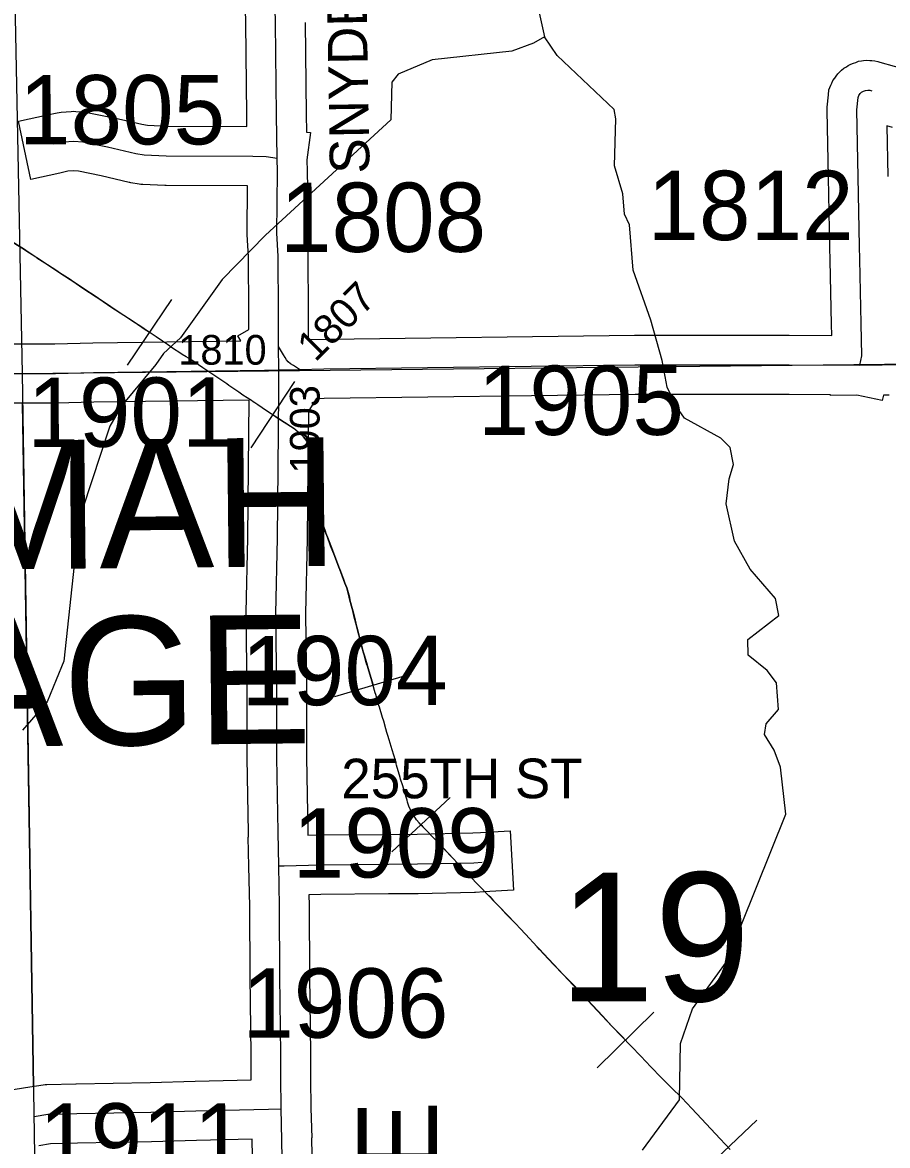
# Model space of a CAD drawing. Extents: x 23.6 to 68.7, y -63 to -29.
# Drawn here: x 50.662 to 51.536, y -49.268 to -48.134 of the extents above; entities that cross this region are included whole.
import ezdxf

# ---------------------------------------------------------------- set-up
doc = ezdxf.new("R2010")
doc.units = 0
for name, color, linetype in [('tdCoCorpTxt', 7, 'Continuous'), ('tdCoHydroRiver', 7, 'Continuous'), ('tdCoPipe', 7, 'Continuous'), ('tdCoSecRdNmbr', 7, 'Continuous'), ('tdCoSecRdTxt', 7, 'Continuous'), ('tdCoSecRteBand', 7, 'Continuous'), ('tdCoSecRteCL', 7, 'Continuous'), ('tdCoSectLine', 7, 'Continuous'), ('tdCoSectLinePart', 7, 'Continuous'), ('tdCoSectNmbr', 7, 'Continuous'), ('tdCoSurfGravel', 7, 'Continuous'), ('tdCoTwpBndry', 7, 'Continuous'), ('tdCoTwpBndryShd', 7, 'Continuous')]:
    doc.layers.add(name, color=color, linetype=linetype)

msp = doc.modelspace()

# ---------------------------------------------------------------- linework, layer by layer
at = {"layer": 'tdCoHydroRiver'}
for points in [[(51.5168, -47.6063), (51.4729, -47.6305), (51.4429, -47.6356), (51.4303, -47.6325), (51.4129, -47.6312), (51.415, -47.6848), (51.4042, -47.7054), (51.384, -47.7309), (51.2793, -47.8331), (51.2543, -47.8492), (51.2121, -47.8922), (51.1935, -47.9209), (51.1972, -47.9698), (51.1862, -47.9809), (51.1723, -48.0079), (51.1697, -48.0585), (51.1897, -48.1482)], [(51.1897, -48.1482), (51.1787, -48.1546), (51.1567, -48.1628), (51.0763, -48.1716), (51.0417, -48.1861), (51.0355, -48.1941), (51.0343, -48.232), (50.9077, -48.3486), (50.864, -48.3933), (50.822, -48.4522), (50.8048, -48.4681), (50.7971, -48.4793), (50.7628, -48.5207), (50.7504, -48.5414), (50.7229, -48.6253), (50.7185, -48.6522), (50.717, -48.6601), (50.7041, -48.7787), (50.6964, -48.7977), (50.6871, -48.8199), (50.6622, -48.8486)], [(51.2888, -49.2726), (51.3261, -49.2217), (51.3271, -49.1649), (51.3393, -49.13), (51.3735, -49.0823), (51.4335, -48.9332), (51.4282, -48.8859), (51.4217, -48.8686), (51.412, -48.853), (51.4135, -48.8419), (51.426, -48.8276), (51.4241, -48.8007), (51.4145, -48.7882), (51.3954, -48.7726), (51.3952, -48.7569), (51.4265, -48.7328), (51.4232, -48.7155), (51.3976, -48.6858), (51.3815, -48.6576), (51.3732, -48.6198), (51.3761, -48.5945), (51.3807, -48.5802), (51.3773, -48.5629), (51.3677, -48.5535), (51.3312, -48.5334), (51.3232, -48.5224), (51.3135, -48.502), (51.3085, -48.4752), (51.297, -48.4343), (51.2791, -48.384), (51.2754, -48.3383), (51.2705, -48.3273), (51.2687, -48.3068), (51.2605, -48.2785), (51.2616, -48.2311), (51.2599, -48.2216), (51.2025, -48.167), (51.1897, -48.1482)]]:
    msp.add_lwpolyline(points, dxfattribs=at)
at = {"layer": 'tdCoPipe'}
for p, q in [((50.7683, -48.4799), (50.8131, -48.4134)), ((50.8934, -48.5635), (50.9374, -48.4965)), ((50.978, -48.8143), (51.0549, -48.7916)), ((51.0355, -48.9712), (51.0943, -48.9166)), ((51.2428, -49.1895), (51.3001, -49.1334)), ((51.3461, -49.2973), (51.4043, -49.2422))]:
    msp.add_line(p, q, dxfattribs=at)
for points in [[(51.3772, -49.272), (51.3671, -49.2613), (51.3576, -49.2511), (51.3482, -49.2408), (51.3385, -49.2304), (51.3284, -49.2198), (51.3178, -49.2094), (51.3075, -49.1991), (51.2972, -49.1883), (51.2871, -49.1777), (51.2773, -49.1676), (51.2679, -49.1579), (51.2577, -49.1473), (51.248, -49.1371), (51.2383, -49.1266), (51.2282, -49.1158), (51.2187, -49.1059), (51.2084, -49.0953), (51.1989, -49.0852), (51.189, -49.0746), (51.1846, -49.0698), (51.1824, -49.0674), (51.1783, -49.0628), (51.1744, -49.0587), (51.1705, -49.0546), (51.165, -49.0488), (51.1608, -49.0442), (51.1593, -49.0428), (51.1524, -49.0357), (51.1506, -49.0338), (51.1451, -49.0279), (51.1405, -49.0232), (51.1382, -49.0208), (51.1343, -49.0167), (51.1313, -49.0136), (51.1253, -49.0073), (51.122, -49.0039), (51.1152, -48.9968), (51.1117, -48.9931), (51.1014, -48.9824), (51.0976, -48.9784), (51.0874, -48.9677), (51.0833, -48.9634), (51.0771, -48.9569), (51.0754, -48.9552), (51.072, -48.9516), (51.0682, -48.9475), (51.0668, -48.9461), (51.0655, -48.9447), (51.063, -48.9419), (51.0603, -48.9389), (51.0568, -48.933), (51.0549, -48.9298), (51.053, -48.9262), (51.0514, -48.9212), (51.0508, -48.9191), (51.0499, -48.916), (51.0471, -48.9069), (51.0464, -48.9047), (51.0443, -48.8978), (51.0439, -48.8962), (51.0403, -48.8839), (51.0399, -48.8825), (51.0397, -48.8812), (51.039, -48.8791), (51.0358, -48.8683), (51.0328, -48.8582), (51.0315, -48.8539), (51.0305, -48.8509), (51.0295, -48.847), (51.0272, -48.8395), (51.026, -48.8355), (51.0229, -48.8251), (51.0224, -48.8234), (51.0192, -48.8124), (51.0187, -48.8108), (51.0145, -48.7964), (51.0122, -48.7885), (51.0107, -48.7838), (51.0103, -48.7825), (51.0096, -48.7801), (51.0074, -48.7724), (51.0065, -48.7694), (51.0057, -48.7668), (51.0027, -48.7549), (51.002, -48.7523), (51, -48.7445), (50.9994, -48.7417), (50.999, -48.7404), (50.9975, -48.7343), (50.9959, -48.728), (50.9952, -48.7255), (50.993, -48.7172), (50.9924, -48.7143), (50.9899, -48.7048), (50.988, -48.6999), (50.9866, -48.6962), (50.9828, -48.6862), (50.9819, -48.6839), (50.9774, -48.6722), (50.9736, -48.6622), (50.9704, -48.6537), (50.9687, -48.6496), (50.9682, -48.6483), (50.9659, -48.6416), (50.965, -48.6367), (50.9647, -48.6338), (50.9641, -48.6295), (50.9631, -48.6225), (50.9627, -48.619), (50.962, -48.6144), (50.9606, -48.6042), (50.9604, -48.6023), (50.9598, -48.5986), (50.9587, -48.5894), (50.9582, -48.5849), (50.9575, -48.5802), (50.9567, -48.5751), (50.9552, -48.569), (50.9533, -48.5633), (50.9509, -48.5586), (50.9488, -48.5556), (50.9462, -48.5522), (50.9424, -48.5488), (50.9408, -48.5475), (50.9365, -48.5439), (50.9328, -48.5415), (50.9204, -48.5334), (50.9079, -48.5252), (50.9044, -48.5228), (50.8999, -48.52), (50.8969, -48.518), (50.8954, -48.517), (50.8935, -48.5157), (50.885, -48.51), (50.8809, -48.5072), (50.8709, -48.5004), (50.8686, -48.4988), (50.8565, -48.4906), (50.8444, -48.4824), (50.8323, -48.4743), (50.8278, -48.4713), (50.8237, -48.469), (50.8212, -48.4674), (50.8148, -48.4632), (50.8088, -48.4591), (50.8037, -48.4556), (50.7974, -48.4513), (50.7853, -48.4431), (50.7828, -48.4414), (50.7729, -48.435), (50.7607, -48.427), (50.7515, -48.4208), (50.7482, -48.4186), (50.7392, -48.4127), (50.7368, -48.411), (50.7243, -48.4029), (50.7198, -48.3997), (50.7119, -48.3944), (50.7105, -48.3935), (50.6998, -48.3866), (50.6971, -48.3847), (50.6874, -48.3784), (50.6769, -48.3715), (50.6757, -48.3707), (50.6656, -48.364), (50.6643, -48.3632), (50.652, -48.3552)], [(50.652, -48.3552), (50.6644, -48.3632), (50.6656, -48.364), (50.6757, -48.3706), (50.6769, -48.3714), (50.6874, -48.3783), (50.6971, -48.3847), (50.6999, -48.3865), (50.7105, -48.3934), (50.712, -48.3944), (50.7198, -48.3997), (50.7244, -48.4028), (50.7368, -48.4109), (50.7393, -48.4127), (50.7482, -48.4186), (50.7515, -48.4208), (50.7608, -48.427), (50.773, -48.4349), (50.7828, -48.4414), (50.7853, -48.443), (50.7907, -48.4467)], [(50.9154, -48.53), (50.9204, -48.5333), (50.9329, -48.5415), (50.9366, -48.5438), (50.9408, -48.5475), (50.9425, -48.5488), (50.9462, -48.5521), (50.9488, -48.5555), (50.9509, -48.5586), (50.9534, -48.5633), (50.9553, -48.569), (50.9568, -48.5751), (50.9576, -48.5802), (50.9583, -48.5849), (50.9588, -48.5894), (50.9599, -48.5986), (50.9605, -48.6023), (50.9606, -48.6042), (50.9621, -48.6144), (50.9627, -48.619), (50.9632, -48.6225), (50.9642, -48.6295), (50.9647, -48.6338), (50.9651, -48.6367), (50.966, -48.6416), (50.9683, -48.6483), (50.9688, -48.6496), (50.9705, -48.6537), (50.9737, -48.6622), (50.9775, -48.6722), (50.982, -48.6839), (50.9828, -48.6861), (50.9866, -48.6961), (50.9881, -48.6999), (50.9899, -48.7048), (50.9925, -48.7142), (50.9931, -48.7172), (50.9953, -48.7255), (50.9959, -48.728), (50.9976, -48.7342), (50.9991, -48.7404), (50.9994, -48.7417), (51.0001, -48.7445), (51.0021, -48.7523), (51.0028, -48.7548), (51.0058, -48.7668), (51.0065, -48.7694), (51.0074, -48.7724), (51.0097, -48.7801), (51.0104, -48.7825), (51.0107, -48.7837), (51.0122, -48.7885), (51.0145, -48.7964), (51.0165, -48.8029)], [(51.0649, -48.9439), (51.0656, -48.9447), (51.0669, -48.946), (51.0682, -48.9475), (51.0721, -48.9515), (51.0755, -48.9551), (51.0771, -48.9569), (51.0833, -48.9633), (51.0875, -48.9677), (51.0976, -48.9783), (51.1015, -48.9823), (51.1117, -48.9931), (51.1152, -48.9968), (51.1221, -49.0039), (51.1253, -49.0072), (51.1314, -49.0136), (51.1343, -49.0166), (51.1382, -49.0208), (51.1405, -49.0232), (51.1451, -49.0279), (51.1506, -49.0337), (51.1525, -49.0357), (51.1594, -49.0427), (51.1608, -49.0441), (51.1651, -49.0488), (51.1705, -49.0545), (51.1744, -49.0587), (51.1783, -49.0628), (51.1824, -49.0673), (51.1847, -49.0697), (51.1891, -49.0745), (51.199, -49.0851), (51.2085, -49.0952), (51.2188, -49.1058), (51.2283, -49.1157), (51.2384, -49.1266), (51.2481, -49.137), (51.2577, -49.1473), (51.268, -49.1579), (51.2714, -49.1614)]]:
    msp.add_lwpolyline(points, dxfattribs=at)
at = {"layer": 'tdCoSecRteBand'}
for points in [[(50.6469, -48.4583), (50.6951, -48.4583), (50.7332, -48.4573), (50.7333, -48.4573), (50.7335, -48.4573), (50.8829, -48.4552), (50.88, -48.4503), (50.8909, -48.4438), (50.8908, -48.4266), (50.8908, -48.4265), (50.8908, -48.4265), (50.8905, -48.3706), (50.8893, -48.3479), (50.8893, -48.347), (50.8893, -48.3462), (50.8897, -48.2988), (50.8074, -48.2985), (50.8068, -48.2985), (50.8062, -48.2985), (50.7839, -48.2975), (50.7819, -48.2974), (50.78, -48.2971), (50.7716, -48.2956), (50.7708, -48.2955), (50.7701, -48.2953), (50.7417, -48.2888), (50.719, -48.284), (50.7141, -48.2836), (50.708, -48.2841), (50.7001, -48.2858), (50.6708, -48.2922), (50.6581, -48.2335), (50.6874, -48.2272), (50.6973, -48.2251), (50.6993, -48.2246), (50.7013, -48.2245), (50.7116, -48.2237), (50.7139, -48.2235), (50.7161, -48.2236), (50.7253, -48.2243), (50.7274, -48.2244), (50.7294, -48.2249), (50.7544, -48.2301), (50.7546, -48.2302), (50.7549, -48.2302), (50.7828, -48.2366), (50.7885, -48.2376), (50.8083, -48.2385), (50.889, -48.2388), (50.8888, -48.2274), (50.8888, -48.2273), (50.8888, -48.2272), (50.888, -48.1346), (50.8857, -48.0332)], [(50.948, -48.1337), (50.948, -48.1339), (50.9488, -48.2265), (50.9491, -48.2445), (50.9533, -48.245), (50.9496, -48.2725), (50.9498, -48.2841), (50.9498, -48.2845), (50.9501, -48.3003), (50.9497, -48.3003), (50.9493, -48.3458), (50.9504, -48.3683), (50.9505, -48.3689), (50.9505, -48.3696), (50.9508, -48.4261), (50.9508, -48.4307), (50.9509, -48.4307), (50.951, -48.4455), (50.951, -48.4455), (50.951, -48.4456), (50.951, -48.4526), (50.9518, -48.4539), (50.9717, -48.4535), (50.9717, -48.4536), (51.2805, -48.4494), (51.2807, -48.4494), (51.2809, -48.4494), (51.4368, -48.4494), (51.4369, -48.4494), (51.437, -48.4494), (51.4799, -48.4498), (51.4797, -48.4384), (51.4784, -48.3741), (51.4779, -48.3607), (51.4779, -48.3605), (51.4779, -48.3602), (51.4766, -48.2905), (51.4753, -48.2226), (51.4752, -48.221), (51.4754, -48.2193), (51.4765, -48.2067), (51.477, -48.2017), (51.479, -48.1971), (51.4799, -48.1952), (51.4811, -48.1924), (51.4829, -48.1899), (51.4842, -48.1881), (51.486, -48.1857), (51.4882, -48.1836), (51.4898, -48.1821), (51.4921, -48.18), (51.4947, -48.1785), (51.4965, -48.1774), (51.4991, -48.1758), (51.502, -48.1748), (51.5041, -48.1741), (51.507, -48.173), (51.51, -48.1726), (51.5121, -48.1723), (51.5151, -48.1719), (51.5182, -48.1721), (51.5204, -48.1723), (51.5234, -48.1725), (51.5263, -48.1733), (51.5284, -48.1739), (51.5573, -48.1819)], [(51.5413, -48.2397), (51.5356, -48.2382), (51.5366, -48.2893)], [(50.64, -49.2134), (50.6697, -49.2088), (50.6832, -49.2067), (50.6851, -49.2064), (50.687, -49.2064), (50.7162, -49.2056), (50.7164, -49.2056), (50.7165, -49.2056), (50.7912, -49.2041), (50.8367, -49.2029), (50.8367, -49.2029), (50.8367, -49.2029), (50.8933, -49.2015), (50.8933, -49.1988), (50.8933, -49.1986), (50.8933, -49.1984), (50.8933, -49.1757), (50.8923, -49.0973), (50.8923, -49.0972), (50.8923, -49.0971), (50.8919, -49.0261), (50.8911, -48.9862), (50.8902, -48.9564), (50.8906, -48.9564), (50.8905, -48.952), (50.8905, -48.952), (50.8905, -48.9519), (50.8893, -48.8766), (50.8893, -48.8764), (50.8893, -48.8761), (50.8893, -48.8094), (50.8882, -48.7309), (50.8882, -48.7303), (50.8882, -48.7297), (50.89, -48.6542), (50.8906, -48.5835), (50.8912, -48.5151), (50.7345, -48.5173), (50.6962, -48.5183), (50.6959, -48.5183), (50.6955, -48.5183), (50.6471, -48.5183)], [(51.5378, -48.5102), (51.5321, -48.5102), (51.5309, -48.5157), (51.5051, -48.5101), (51.4786, -48.5105), (51.4786, -48.5098), (51.4367, -48.5094), (51.2811, -48.5094), (50.9672, -48.5136), (50.9591, -48.5138), (50.9517, -48.5255), (50.9511, -48.5251), (50.9506, -48.5841), (50.9506, -48.5841), (50.9506, -48.5841), (50.95, -48.655), (50.95, -48.6552), (50.95, -48.6554), (50.9482, -48.7306), (50.9493, -48.8088), (50.9493, -48.809), (50.9493, -48.8092), (50.9493, -48.8759), (50.9505, -48.9509), (50.9505, -48.9546), (50.9625, -48.9543), (50.9628, -48.9543), (50.9631, -48.9543), (51.0316, -48.9538), (51.0317, -48.9538), (51.0317, -48.9538), (51.061, -48.9536), (51.1171, -48.9523), (51.125, -48.9519), (51.1549, -48.9501), (51.1584, -49.01), (51.1285, -49.0118), (51.1201, -49.0123), (51.1196, -49.0123), (51.119, -49.0123), (51.0621, -49.0136), (51.0619, -49.0136), (51.0616, -49.0136), (51.032, -49.0138), (50.9638, -49.0143), (50.9517, -49.0146), (50.9517, -49.0149), (50.9519, -49.0251), (50.9519, -49.0254), (50.9519, -49.0256), (50.9523, -49.0967), (50.9533, -49.1751), (50.9533, -49.1753), (50.9533, -49.1755), (50.9533, -49.1982), (50.9533, -49.2004), (50.9537, -49.2302), (50.9545, -49.26), (50.9542, -49.26), (50.9554, -49.3144)], [(50.8954, -49.3156), (50.8942, -49.2615), (50.8382, -49.2629), (50.7927, -49.2641), (50.7926, -49.2641), (50.7925, -49.2641), (50.7178, -49.2656), (50.6905, -49.2663), (50.6788, -49.2681)]]:
    msp.add_lwpolyline(points, dxfattribs=at)
at = {"layer": 'tdCoSecRteCL'}
for q in [(50.921, -48.4609), (50.9423, -48.4841)]:
    msp.add_line((50.9212, -48.4846), q, dxfattribs=at)
for points in [[(50.9196, -48.2708), (50.9188, -48.2269), (50.918, -48.1342), (50.9157, -48.0326), (50.9144, -47.9535), (50.9136, -47.8802), (50.9122, -47.8026), (50.9118, -47.7467)], [(51.5081, -48.48), (51.5102, -48.4703), (51.5097, -48.4379), (51.5084, -48.3733), (51.5079, -48.3596), (51.5066, -48.2899), (51.5053, -48.222), (51.5064, -48.2094), (51.5073, -48.2074), (51.5086, -48.2056), (51.5101, -48.2042), (51.512, -48.2031), (51.514, -48.2024), (51.5162, -48.2021), (51.5183, -48.2022), (51.5204, -48.2028)], [(50.6938, -48.2565), (50.7036, -48.2544), (50.714, -48.2536), (50.7232, -48.2542), (50.7482, -48.2595), (50.7768, -48.2661), (50.7852, -48.2675), (50.8075, -48.2685), (50.895, -48.2688), (50.9085, -48.2693), (50.9196, -48.2708)], [(50.921, -48.4609), (50.921, -48.4457), (50.9208, -48.4263), (50.9205, -48.3698), (50.9193, -48.3464), (50.9198, -48.2846), (50.9196, -48.2708)], [(50.9423, -48.4841), (50.9362, -48.4803), (50.9332, -48.4784), (50.9308, -48.4764), (50.929, -48.4744), (50.9275, -48.4722), (50.9261, -48.4694), (50.921, -48.4609)], [(50.2167, -48.4955), (50.4198, -48.492), (50.4831, -48.4908), (50.5547, -48.4905), (50.5936, -48.4891), (50.6469, -48.4883), (50.6955, -48.4883), (50.7339, -48.4873), (50.9068, -48.4849), (50.9212, -48.4846)], [(50.9211, -48.9855), (50.9205, -48.9514), (50.9193, -48.8761), (50.9193, -48.8092), (50.9182, -48.7305), (50.92, -48.6547), (50.9206, -48.5838), (50.9213, -48.5074), (50.9212, -48.4862), (50.9212, -48.4846)], [(50.9423, -48.4841), (50.9667, -48.4836), (51.2809, -48.4794), (51.4368, -48.4794), (51.5081, -48.48)], [(51.5081, -48.48), (51.6444, -48.4777), (51.75, -48.475), (51.9174, -48.4755), (52.1699, -48.4748)], [(50.9211, -48.9855), (50.9268, -48.9853), (50.9633, -48.9843), (51.0319, -48.9838), (51.0614, -48.9836), (51.1183, -48.9823), (51.1267, -48.9818)], [(50.9237, -49.2308), (50.9233, -49.1984), (50.9233, -49.1755), (50.9223, -49.0969), (50.9219, -49.0257), (50.9211, -48.9855)], [(50.6742, -49.2385), (50.6878, -49.2364), (50.7171, -49.2356), (50.7919, -49.2341), (50.8374, -49.2329), (50.9108, -49.2311), (50.9237, -49.2308)], [(50.9362, -49.9619), (50.9359, -49.9267), (50.9351, -49.8714), (50.9336, -49.783), (50.9325, -49.7037), (50.9313, -49.6301), (50.9297, -49.5428), (50.928, -49.4701), (50.9265, -49.3887), (50.9254, -49.3151), (50.9239, -49.246), (50.9237, -49.2308)]]:
    msp.add_lwpolyline(points, dxfattribs=at)
at = {"layer": 'tdCoSectLine'}
for points in [[(50.6618, -48.4883), (51.6577, -48.4774)], [(50.6618, -48.4883), (50.6779, -49.4907)]]:
    msp.add_lwpolyline(points, dxfattribs=at)
at = {"layer": 'tdCoSectLinePart'}
msp.add_lwpolyline([(50.6623, -48.5186), (50.6734, -49.2084)], dxfattribs=at)
at = {"layer": 'tdCoSurfGravel'}
for points in [[(50.9254, -49.3151), (50.9239, -49.246), (50.9237, -49.2308), (50.9233, -49.1984), (50.9233, -49.1755), (50.9223, -49.0969), (50.9219, -49.0257), (50.9211, -48.9855), (50.9205, -48.9514), (50.9193, -48.8761), (50.9193, -48.8092), (50.9182, -48.7305), (50.92, -48.6547), (50.9206, -48.5838), (50.9213, -48.5074), (50.9212, -48.4862), (50.9212, -48.4846), (50.921, -48.4609), (50.921, -48.4457), (50.9208, -48.4263), (50.9205, -48.3698), (50.9193, -48.3464), (50.9198, -48.2846), (50.9196, -48.2708), (50.9188, -48.2269), (50.918, -48.1342), (50.9157, -48.0326)], [(51.5081, -48.48), (51.5102, -48.4703), (51.5097, -48.4379), (51.5084, -48.3733), (51.5079, -48.3596), (51.5066, -48.2899), (51.5053, -48.222), (51.5064, -48.2094), (51.5073, -48.2074), (51.5086, -48.2056), (51.5101, -48.2042), (51.512, -48.2031), (51.514, -48.2024), (51.5162, -48.2021), (51.5183, -48.2022), (51.5204, -48.2028)], [(50.6938, -48.2565), (50.7036, -48.2544), (50.714, -48.2536), (50.7232, -48.2542), (50.7482, -48.2595), (50.7768, -48.2661), (50.7852, -48.2675), (50.8075, -48.2685), (50.895, -48.2688), (50.9085, -48.2693), (50.9196, -48.2708)], [(50.9423, -48.4841), (50.9362, -48.4803), (50.9332, -48.4784), (50.9308, -48.4764), (50.929, -48.4744), (50.9275, -48.4722), (50.9261, -48.4694), (50.921, -48.4609)], [(50.9212, -48.4846), (50.9423, -48.4841), (50.9667, -48.4836), (51.2809, -48.4794), (51.4368, -48.4794), (51.5081, -48.48), (51.6444, -48.4777), (51.75, -48.475), (51.9174, -48.4755), (52.1699, -48.4748), (52.2222, -48.4733), (52.2688, -48.4733), (52.3046, -48.4731)], [(50.1639, -48.4944), (50.17, -48.4933), (50.2167, -48.4955), (50.4198, -48.492), (50.4831, -48.4908), (50.5547, -48.4905), (50.5936, -48.4891), (50.6469, -48.4883), (50.6955, -48.4883), (50.7339, -48.4873), (50.9068, -48.4849), (50.9212, -48.4846)], [(50.9211, -48.9855), (50.9268, -48.9853), (50.9633, -48.9843), (51.0319, -48.9838), (51.0614, -48.9836), (51.1183, -48.9823), (51.1267, -48.9818)], [(50.6742, -49.2385), (50.6878, -49.2364), (50.7171, -49.2356), (50.7919, -49.2341), (50.8374, -49.2329), (50.9108, -49.2311), (50.9237, -49.2308)]]:
    msp.add_lwpolyline(points, dxfattribs=at)
at = {"layer": 'tdCoTwpBndry'}
msp.add_lwpolyline([(50.6734, -49.2082), (50.6623, -48.5183)], dxfattribs=at)
at = {"layer": 'tdCoTwpBndryShd'}
msp.add_lwpolyline([(50.5509, -40.5443), (50.5639, -41.5427), (50.569, -42.5417), (50.5871, -43.537), (50.6019, -44.5288), (50.6203, -45.5327), (50.63, -46.4962), (50.6425, -47.4949), (50.6618, -48.4883), (50.6779, -49.4907), (50.6874, -50.4863), (50.7061, -51.4863), (50.7229, -52.5573), (50.7376, -53.5528), (50.7529, -54.5599), (50.7681, -55.5514), (50.7851, -56.5511), (50.7973, -57.5472)], dxfattribs=at)

# ---------------------------------------------------------------- texts
at = {"layer": 'tdCoCorpTxt'}
for s, p in [('KEOMAH', (50.2284, -48.6904)), ('VILLAGE', (50.2302, -48.8692))]:
    msp.add_text(s, height=0.13, rotation=0.6, dxfattribs=at).set_placement(p)
at = {"layer": 'tdCoSecRdNmbr'}
for s, height, rotation, p in [('1805', 0.07, 0.0393, (50.6588, -48.257)), ('1812', 0.07, 0.0395, (51.2937, -48.3536)), ('1808', 0.07, 0.0395, (50.9225, -48.3656)), ('1807', 0.03, 45.0381, (50.9582, -48.4775)), ('1810', 0.03, 0.0394, (50.8197, -48.4794)), ('1905', 0.07, 0.0397, (51.1223, -48.5504)), ('1901', 0.07, 0.0393, (50.6672, -48.5624)), ('1903', 0.03, 90.0374, (50.9625, -48.5893)), ('1904', 0.07, 0.0395, (50.8835, -48.8233)), ('1909', 0.07, 0.0395, (50.9353, -48.9973)), ('1906', 0.07, 0.0395, (50.8843, -49.1591)), ('1911', 0.07, 0.0393, (50.6791, -49.2953))]:
    msp.add_text(s, height=height, rotation=rotation, dxfattribs=at).set_placement(p)
at = {"layer": 'tdCoSecRdTxt'}
for s, height, rotation, p in [('SNYDER AVE', 0.04, 91, (51.013, -48.2862)), ('255TH ST', 0.04, 0.0389, (50.9844, -48.9173)), ('SNYDER AVE', 0.08, 90, (51.081, -49.9128))]:
    msp.add_text(s, height=height, rotation=rotation, dxfattribs=at).set_placement(p)
at = {"layer": 'tdCoSectNmbr'}
msp.add_text('19', height=0.13, rotation=0.0396, dxfattribs=at).set_placement((51.2041, -49.1223))

doc.saveas('drawing.dxf')
